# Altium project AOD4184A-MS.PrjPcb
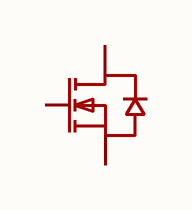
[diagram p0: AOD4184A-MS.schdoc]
1 sheet, 1 parts. Net scope: global (net labels, ports and power ports of the same name join across sheets).

## Sheet AOD4184A-MS.schdoc
size 127 x 101 mm

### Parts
Q?  aod4184a-ms  [TO-252-2_L6.6-W6.1-P4.57-LS9.9-BR-CW]  (value not drawn)

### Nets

Not connected (* = marked no-connect by the designer): Q? 1(G) 2(D) 3(S)

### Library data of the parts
Q? = aod4184a-ms: 数量:1个N沟道;漏源电压(Vdss):40V;连续漏极电流(Id):50A;导通电阻(RDS(on)):8mΩ@10V;耗散功率(Pd):50W;阈值电压(Vgs(th)):2.5V;; Manufacturer: MSKSEMI(美森科); AddInBom: yes; ModelId: ce57f84d66384067af8a68020b6de06d; ModelName: TO-252-2L-3P_L6.6-W6.1-H2.3-LS10.1-P4.6; ModelTransform: 259.842,390.52442,0,90,0,0,-39.39,0,0; Number: 1个N沟道; Drain to Source Voltage: 40V; Current - Continuous Drain(Id): 50A; Pd - Power Dissipation: 50W; Gate Threshold Voltage (Vgs(th)): 2.5V; Gate Charge(Qg): 16.2nC@4.5V; Input Capacitance(Ciss): 1.54nF; Reverse Transfer Capacitance (Crss@Vds): 115pF; Type: N沟道; Output Capacitance(Coss): 171pF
